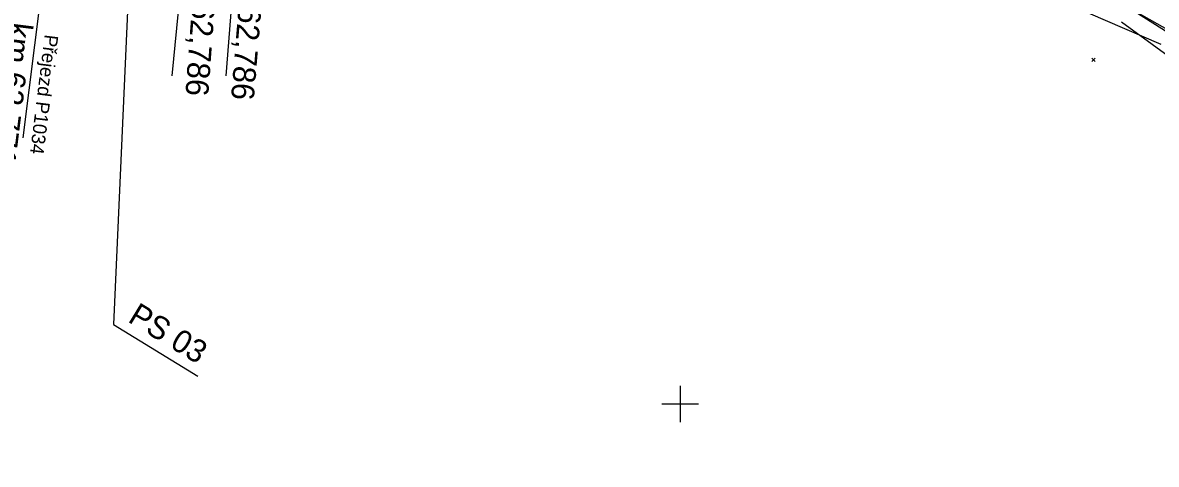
# Model space of a CAD drawing. Extents: x -804899 to -803847, y -1165742 to -1164942.
# Drawn here: x -804772 to -804647.9, y -1165206.6 to -1165158.3 of the extents above; entities that cross this region are included whole.
import ezdxf

# ---------------------------------------------------------------- set-up
doc = ezdxf.new("R2010")
doc.units = 0
for name, color, linetype in [('0381KM061-064P - Vrstva 3', 7, 'Continuous'), ('0381KM061-064P - Vrstva 4', 7, 'Continuous'), ('0381KM061-064P - Vrstva 49', 7, 'Continuous'), ('0381KM061-064P - Vrstva 8', 7, 'Continuous'), ('hran DP - hran DP', 7, 'Continuous'), ('krizky_1000 - Vrstva 1', 7, 'Continuous'), ('SOPS', 7, 'Continuous')]:
    doc.layers.add(name, color=color, linetype=linetype)

msp = doc.modelspace()

# ---------------------------------------------------------------- linework, layer by layer
at = {"layer": '0381KM061-064P - Vrstva 3'}
msp.add_lwpolyline([(-804750.67, -1165118.27), (-804753.55, -1165147.9), (-804748.48, -1165148.39), (-804749.73, -1165164.12)], dxfattribs=at)
at = {"layer": '0381KM061-064P - Vrstva 4'}
msp.add_line((-804765.1, -1165116.15), (-804771.94, -1165170.89), dxfattribs=at)
msp.add_lwpolyline([(-804760.26, -1165118.8), (-804748.39, -1165120.75), (-804721.77, -1165126.98), (-804699.38, -1165134.38), (-804682.72, -1165140.57), (-804673.68, -1165144.67), (-804650.96, -1165156.64), (-804639.65, -1165163.02), (-804626.64, -1165171.43)], dxfattribs=at)
at = {"layer": '0381KM061-064P - Vrstva 49'}
for p, q in [((-804654.61, -1165162.53), (-804654.97, -1165162.18)), ((-804654.61, -1165162.18), (-804654.97, -1165162.53))]:
    msp.add_line(p, q, dxfattribs=at)
for points in [[(-804650.96, -1165156.64), (-804629.95, -1165169.87)], [(-804651.73, -1165158.22), (-804641.24, -1165165.82), (-804629.21, -1165174.28), (-804606.38, -1165188.59), (-804578.69, -1165207.38), (-804546.55, -1165228.41), (-804509.4, -1165252.77), (-804482.02, -1165272.35), (-804454.07, -1165289.87), (-804424.02, -1165310.32)]]:
    msp.add_lwpolyline(points, dxfattribs=at)
at = {"layer": '0381KM061-064P - Vrstva 8'}
msp.add_line((-804751.48, -1165121.84), (-804755.65, -1165164.12), dxfattribs=at)
at = {"layer": 'hran DP - hran DP'}
msp.add_line((-804647.39, -1165160.7), (-804728.07, -1165125.68), dxfattribs=at)
at = {"layer": 'krizky_1000 - Vrstva 1'}
for points in [[(-804700, -1165198), (-804700, -1165202)], [(-804702, -1165200), (-804698, -1165200)]]:
    msp.add_lwpolyline(points, dxfattribs=at)
at = {"layer": 'SOPS'}
msp.add_lwpolyline([(-804758.92, -1165121.97), (-804762.02, -1165191.31), (-804752.78, -1165196.94)], dxfattribs=at)

# ---------------------------------------------------------------- texts
at = {"layer": '0381KM061-064P - Vrstva 3'}
msp.add_text('km 62,786', height=2.5, rotation=265.3169, dxfattribs=at).set_placement((-804747.89, -1165151.1))
at = {"layer": '0381KM061-064P - Vrstva 4'}
for s, height, p in [('km 62,771', 2.5, (-804773.35, -1165158.16)), ('Přejezd P1034', 1.5, (-804769.54, -1165159.54))]:
    msp.add_text(s, height=height, rotation=262.8793, dxfattribs=at).set_placement(p)
at = {"layer": '0381KM061-064P - Vrstva 8'}
msp.add_text('km 62,786', height=2.5, rotation=265.7808, dxfattribs=at).set_placement((-804753.01, -1165150.66))
at = {"layer": 'SOPS'}
msp.add_text('PS 03', height=2.5, rotation=328.6338, dxfattribs=at).set_placement((-804760.56, -1165190.95))

doc.saveas('drawing.dxf')
